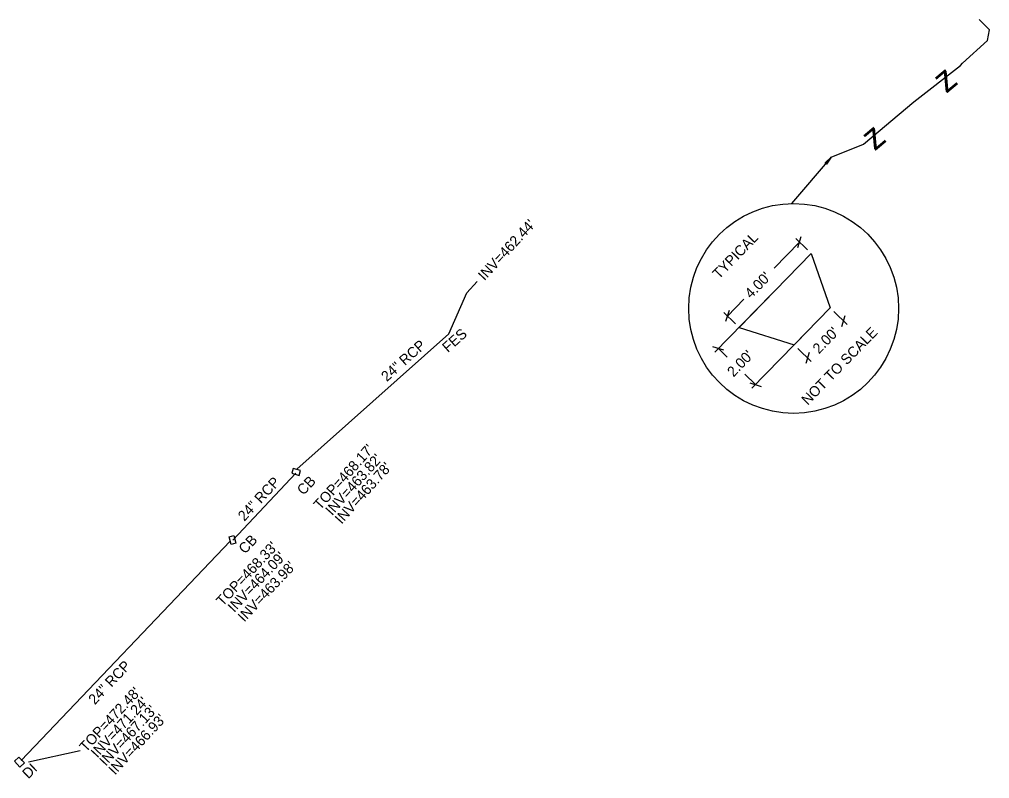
# Model space of a CAD drawing. Extents: x 1975859 to 1978323, y 778892 to 782836.
# Drawn here: x 1976411.8 to 1976787.3, y 779591.4 to 779885.3 of the extents above; entities that cross this region are included whole.
import ezdxf

# ---------------------------------------------------------------- set-up
doc = ezdxf.new("R2010")
doc.units = 0
for name, color, linetype in [('Exist Structure Minor Catch Basin', 7, 'Continuous'), ('Exist Structure Minor Catch Basin Text', 7, 'Continuous'), ('Exist Structure Minor Drop Inlet', 7, 'Continuous'), ('Exist Structure Minor Drop Inlet Leader', 7, 'Continuous'), ('Exist Structure Minor Drop Inlet Text', 7, 'Continuous'), ('Exist Structure Minor Pipes HDPE 8 Inch Invert', 7, 'Continuous'), ('Exist Structure Minor Pipes RCP 24 Inch', 7, 'Continuous'), ('Exist Structure Minor Pipes RCP 24 Inch Invert', 7, 'Continuous'), ('Exist Structure Minor Pipes RCP 24 Inch Text', 7, 'Continuous'), ('Scratch_Level_8', 7, 'Continuous')]:
    doc.layers.add(name, color=color, linetype=linetype)

msp = doc.modelspace()

# ---------------------------------------------------------------- linework, layer by layer
at = {"layer": 'Exist Structure Minor Catch Basin'}
for points in [[(1976517.2, 779709.62), (1976520.05, 779708.77), (1976520.61, 779710.65), (1976517.76, 779711.5)], [(1976494.81, 779685.53), (1976495.59, 779682.56), (1976493.7, 779682.06), (1976492.92, 779685.03)]]:
    msp.add_lwpolyline(points, close=True, dxfattribs=at)
at = {"layer": 'Exist Structure Minor Drop Inlet'}
msp.add_lwpolyline([(1976411.57, 779599.79), (1976413.7, 779597.5), (1976411.95, 779595.88), (1976409.83, 779598.18)], close=True, dxfattribs=at)
at = {"layer": 'Exist Structure Minor Drop Inlet Leader'}
msp.add_lwpolyline([(1976415.25, 779597.91), (1976435.23, 779602.33)], dxfattribs=at)
at = {"layer": 'Exist Structure Minor Pipes RCP 24 Inch'}
for p, q in [((1976577.99, 779763.59), (1976519.2, 779711.2)), ((1976518.76, 779709.61), (1976494.45, 779683.68)), ((1976412.51, 779598.41), (1976493.33, 779683.32))]:
    msp.add_line(p, q, dxfattribs=at)
at = {"layer": 'Exist Structure Minor Pipes RCP 24 Inch Invert'}
msp.add_lwpolyline([(1976577.99, 779763.59), (1976584.91, 779779.42), (1976588.98, 779783.83)], dxfattribs=at)
at = {"layer": 'Scratch_Level_8'}
for p, q in [((1976725.98, 779831.91), (1976710.58, 779814.02)), ((1976724.02, 779829.23), (1976723.61, 779829.57)), ((1976723.68, 779829.58), (1976724.03, 779829.64)), ((1976724.03, 779829.64), (1976723.71, 779829.5)), ((1976724.03, 779829.64), (1976723.77, 779829.44)), ((1976724.03, 779829.64), (1976723.86, 779829.36)), ((1976724.03, 779829.64), (1976723.94, 779829.29)), ((1976724.03, 779829.64), (1976724.01, 779829.29)), ((1976713.74, 779799.12), (1976703.92, 779789.04)), ((1976716.83, 779796.12), (1976712.31, 779800.52)), ((1976713.06, 779796.99), (1976714.42, 779801.25)), ((1976690.34, 779766.07), (1976718.26, 779794.72)), ((1976718.26, 779794.72), (1976725.6, 779773.6)), ((1976702.91, 779778.96), (1976680.99, 779756.47)), ((1976685.83, 779770.47), (1976692.15, 779776.96)), ((1976686.51, 779772.6), (1976685.15, 779768.34)), ((1976711.65, 779759.28), (1976725.6, 779773.6)), ((1976688.91, 779767.47), (1976684.4, 779771.87)), ((1976727.04, 779772.2), (1976732.21, 779767.16)), ((1976730.1, 779766.43), (1976731.46, 779770.69)), ((1976690.34, 779766.07), (1976711.65, 779759.28)), ((1976717.23, 779765.01), (1976695.31, 779742.51)), ((1976684.51, 779757.22), (1976680.25, 779758.58)), ((1976682.38, 779757.9), (1976685.76, 779754.61)), ((1976713.08, 779757.88), (1976718.25, 779752.84)), ((1976717.5, 779756.37), (1976716.14, 779752.1)), ((1976696.71, 779743.94), (1976692.53, 779748.01)), ((1976694.57, 779744.62), (1976698.84, 779743.26))]:
    msp.add_line(p, q, dxfattribs=at)
for points in [[(1976725.98, 779831.91), (1976738.49, 779836.98), (1976757.97, 779853.36), (1976776, 779867.43), (1976776.77, 779868.38), (1976786.52, 779877.12), (1976787.32, 779881.19), (1976783.22, 779885.28)], [(1976724.07, 779829.38), (1976725.98, 779831.91), (1976724.02, 779829.23), (1976724.01, 779829.29), (1976724.07, 779829.38), (1976724.03, 779829.64), (1976723.76, 779829.65), (1976723.68, 779829.58), (1976723.61, 779829.57), (1976725.98, 779831.91), (1976723.76, 779829.65)], [(1976724.02, 779829.23), (1976724.24, 779829.34), (1976725.98, 779831.91), (1976723.69, 779829.81), (1976723.61, 779829.57)], [(1976723.65, 779829.69), (1976725.98, 779831.91), (1976724.13, 779829.28)], [(1976725.86, 779831.79), (1976725.92, 779831.84), (1976725.87, 779831.76), (1976725.81, 779831.69), (1976725.86, 779831.77), (1976725.79, 779831.72), (1976725.73, 779831.65), (1976725.8, 779831.7), (1976725.75, 779831.61), (1976725.7, 779831.54), (1976725.74, 779831.63), (1976725.66, 779831.59), (1976725.6, 779831.52), (1976725.67, 779831.56), (1976725.64, 779831.46), (1976725.59, 779831.39), (1976725.61, 779831.49), (1976725.53, 779831.45), (1976725.46, 779831.39), (1976725.55, 779831.42), (1976725.53, 779831.31), (1976725.47, 779831.24), (1976725.49, 779831.34), (1976725.4, 779831.32), (1976725.33, 779831.25), (1976725.43, 779831.27), (1976725.42, 779831.17), (1976725.36, 779831.09), (1976725.37, 779831.2), (1976725.27, 779831.19), (1976725.2, 779831.12), (1976725.31, 779831.13), (1976725.3, 779831.02), (1976725.25, 779830.94), (1976725.25, 779831.06), (1976725.14, 779831.05), (1976725.07, 779830.99), (1976725.19, 779830.99), (1976725.19, 779830.87), (1976725.13, 779830.79), (1976725.12, 779830.92), (1976725, 779830.92), (1976724.94, 779830.85), (1976725.06, 779830.85), (1976725.08, 779830.72), (1976725.02, 779830.64), (1976725, 779830.78), (1976724.87, 779830.79), (1976724.81, 779830.72), (1976724.94, 779830.71), (1976724.97, 779830.57), (1976724.91, 779830.49), (1976724.88, 779830.64), (1976724.74, 779830.65), (1976724.68, 779830.59), (1976724.82, 779830.56), (1976724.85, 779830.42), (1976724.8, 779830.34), (1976724.76, 779830.49), (1976724.61, 779830.52), (1976724.54, 779830.45), (1976724.7, 779830.42), (1976724.74, 779830.27), (1976724.68, 779830.19), (1976724.64, 779830.35), (1976724.48, 779830.39), (1976724.41, 779830.32), (1976724.57, 779830.28), (1976724.63, 779830.12), (1976724.57, 779830.04), (1976724.52, 779830.2), (1976724.35, 779830.25), (1976724.28, 779830.19), (1976724.45, 779830.14), (1976724.52, 779829.97), (1976724.46, 779829.89), (1976724.39, 779830.07), (1976724.22, 779830.12), (1976724.15, 779830.05), (1976724.33, 779830), (1976724.4, 779829.82), (1976724.35, 779829.74), (1976724.27, 779829.93), (1976724.08, 779829.99), (1976724.02, 779829.92), (1976724.21, 779829.85), (1976724.29, 779829.67), (1976724.23, 779829.59), (1976724.15, 779829.78), (1976723.95, 779829.85), (1976723.89, 779829.79), (1976724.09, 779829.71), (1976724.18, 779829.52), (1976724.12, 779829.44), (1976724.03, 779829.64), (1976723.82, 779829.72)]]:
    msp.add_lwpolyline(points, dxfattribs=at)
msp.add_circle((1976711.46, 779773.42), 40.62, dxfattribs=at)

# ---------------------------------------------------------------- texts
at = {"layer": 'Exist Structure Minor Catch Basin Text'}
for s, rotation, p in [("TOP=468.17'", 48.0587, (1976528.23, 779695.17)), ('CB', 46.399, (1976521.7, 779700.88)), ("TOP=468.33'", 46.6366, (1976490.44, 779657.91)), ('CB', 46.3322, (1976499.08, 779678.16))]:
    msp.add_text(s, height=4, rotation=rotation, dxfattribs=at).set_placement(p)
at = {"layer": 'Exist Structure Minor Drop Inlet Text'}
for s, rotation, p in [("TOP=472.48'", 47.0826, (1976437.54, 779601.45)), ('DI', 43.9191, (1976415.19, 779591.14))]:
    msp.add_text(s, height=4, rotation=rotation, dxfattribs=at).set_placement(p)
at = {"layer": 'Exist Structure Minor Pipes HDPE 8 Inch Invert'}
msp.add_text("INV=471.24'", height=4, rotation=47.0826, dxfattribs=at).set_placement((1976441.92, 779599.23))
at = {"layer": 'Exist Structure Minor Pipes RCP 24 Inch Invert'}
for s, rotation, p in [("INV=462.44'", 47.2906, (1976591.81, 779783.94)), ("INV=463.82'", 48.0587, (1976532.8, 779693)), ("INV=463.78'", 48.0587, (1976536.46, 779689.71)), ("INV=464.09'", 46.6366, (1976494.88, 779655.53)), ("INV=463.98'", 46.6366, (1976498.81, 779651.81)), ("INV=467.13'", 47.0826, (1976445.21, 779596.04)), ("INV=466.93'", 47.0826, (1976448.76, 779592.63))]:
    msp.add_text(s, height=4, rotation=rotation, dxfattribs=at).set_placement(p)
at = {"layer": 'Exist Structure Minor Pipes RCP 24 Inch Text'}
for s, rotation, p in [('FES', 41.7079, (1976577.64, 779756.13)), ('24" RCP', 41.7079, (1976554, 779744.89)), ('24" RCP', 46.8552, (1976498.87, 779690.85)), ('24" RCP', 46.4116, (1976440.97, 779619.83))]:
    msp.add_text(s, height=4, rotation=rotation, dxfattribs=at).set_placement(p)
at = {"layer": 'Scratch_Level_8'}
for s, height, rotation, p in [('z', 10, 40.0444, (1976770.51, 779856.36)), ('z', 10, 40.0444, (1976742.8, 779834.08)), ('TYPICAL', 4, 45.7394, (1976682.53, 779784.54)), ("4.00'", 4, 45.7394, (1976694.98, 779777)), ('NOT TO SCALE', 4, 45.7394, (1976716.92, 779735.75)), ("2.00'", 4, 45.7394, (1976721.28, 779755.63)), ("2.00'", 4, 45.7394, (1976688.19, 779746.66))]:
    msp.add_text(s, height=height, rotation=rotation, dxfattribs=at).set_placement(p)

doc.saveas('drawing.dxf')
